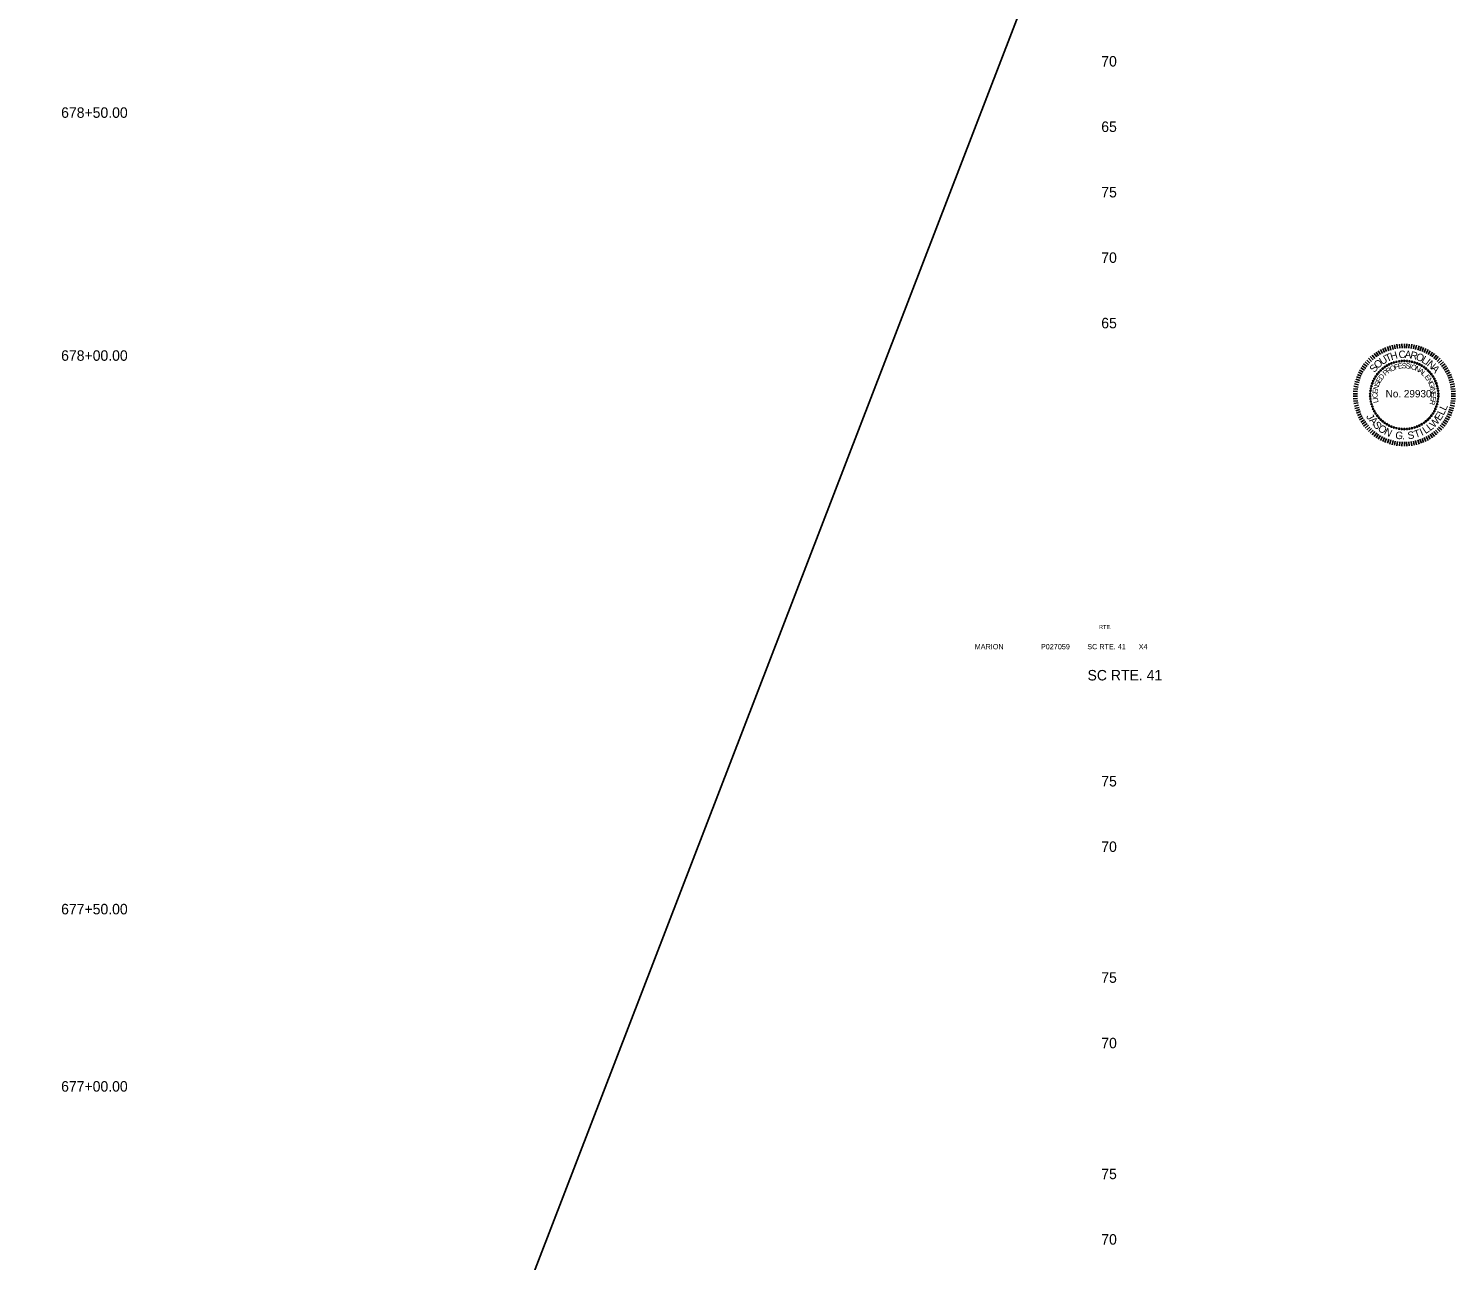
# Model space of a CAD drawing. Extents: x 952 to 1206, y 942 to 2399.
# Drawn here: x 1074.9 to 1184, y 1398.8 to 1492.9 of the extents above; entities that cross this region are included whole.
import ezdxf

# ---------------------------------------------------------------- set-up
doc = ezdxf.new("R2010")
doc.units = 0
for name, color, linetype in [('Default', 7, 'Continuous'), ('RD_SHT_TX', 7, 'Continuous'), ('RD_TX_PEShield', 7, 'Continuous'), ('RD_XS_TX_Elev_EX', 7, 'Continuous'), ('RD_XS_TX_Station', 7, 'Continuous')]:
    doc.layers.add(name, color=color, linetype=linetype)

# ---------------------------------------------------------------- blocks, each defined once
blk = doc.blocks.new('STILLWELL')
at = {"layer": 'RD_TX_PEShield'}
for p, q in [((-18.2, 30), (-19.9, 32.8)), ((-16.7, 30.8), (-18.2, 33.7)), ((-15.1, 31.6), (-16.5, 34.6)), ((-13.6, 32.3), (-14.8, 35.3)), ((-11.9, 32.9), (-13, 36)), ((-10.3, 33.4), (-11.2, 36.6)), ((-8.6, 33.9), (-9.4, 37.1)), ((-6.9, 34.3), (-7.5, 37.5)), ((-5.2, 34.6), (-5.7, 37.8)), ((-3.5, 34.8), (-3.8, 38)), ((-1.8, 34.9), (-1.9, 38.2)), ((0, 34.9), (0, 38.2)), ((1.7, 34.9), (1.9, 38.2)), ((3.4, 34.8), (3.7, 38)), ((5.2, 34.6), (5.6, 37.8)), ((6.9, 34.3), (7.5, 37.5)), ((8.6, 33.9), (9.3, 37.1)), ((10.2, 33.4), (11.2, 36.6)), ((11.9, 32.9), (13, 36)), ((13.5, 32.3), (14.7, 35.3)), ((15.1, 31.6), (16.5, 34.6)), ((16.6, 30.8), (18.2, 33.7)), ((18.2, 30), (19.8, 32.8)), ((-28.5, 20.9), (-31.1, 22.8)), ((-27.4, 22.2), (-29.9, 24.3)), ((-26.3, 23.5), (-28.7, 25.7)), ((-25.1, 24.7), (-27.4, 27.1)), ((-23.8, 25.9), (-26, 28.4)), ((-22.5, 27), (-24.5, 29.6)), ((-21.1, 28.1), (-23, 30.7)), ((-19.7, 29.1), (-21.5, 31.8)), ((19.6, 29.1), (21.4, 31.8)), ((21.1, 28.1), (23, 30.7)), ((22.4, 27), (24.5, 29.6)), ((23.8, 25.9), (25.9, 28.4)), ((25, 24.7), (27.3, 27.1)), ((26.2, 23.5), (28.6, 25.7)), ((27.4, 22.2), (29.9, 24.3)), ((28.5, 20.9), (31.1, 22.8)), ((-34.1, 10.2), (-37.2, 11.2)), ((-33.6, 11.8), (-36.6, 12.9)), ((-32.9, 13.4), (-35.9, 14.7)), ((-32.2, 15), (-35.1, 16.4)), ((-31.4, 16.5), (-34.2, 18.1)), ((-30.5, 18), (-33.3, 19.7)), ((-29.5, 19.4), (-32.2, 21.3)), ((29.5, 19.4), (32.2, 21.3)), ((30.4, 18), (33.2, 19.7)), ((31.3, 16.5), (34.2, 18.1)), ((32.1, 15), (35.1, 16.4)), ((32.9, 13.4), (35.9, 14.7)), ((33.5, 11.8), (36.6, 12.9)), ((34.1, 10.2), (37.2, 11.2)), ((-35.9, -0.1), (-39.2, 0)), ((-35.8, 1.7), (-39.1, 1.9)), ((-35.6, 3.4), (-38.9, 3.8)), ((-35.4, 5.1), (-38.6, 5.7)), ((-35.1, 6.8), (-38.2, 7.5)), ((-34.6, 8.5), (-37.8, 9.4)), ((34.6, 8.5), (37.7, 9.4)), ((35, 6.8), (38.2, 7.5)), ((35.3, 5.1), (38.5, 5.7)), ((35.6, 3.4), (38.8, 3.8)), ((35.7, 1.7), (39, 1.9)), ((35.8, -0.1), (39.1, 0)), ((-35.9, -1.8), (-39.2, -1.9)), ((-35.8, -3.5), (-39.1, -3.8)), ((-35.6, -5.3), (-38.9, -5.6)), ((-35.4, -7), (-38.6, -7.5)), ((-35.1, -8.7), (-38.2, -9.4)), ((-34.6, -10.4), (-37.8, -11.2)), ((34.6, -10.4), (37.7, -11.2)), ((35, -8.7), (38.2, -9.4)), ((35.3, -7), (38.5, -7.5)), ((35.6, -5.3), (38.8, -5.6)), ((35.7, -3.5), (39, -3.8)), ((35.8, -1.8), (39.1, -1.9)), ((-34.1, -12), (-37.2, -13)), ((-33.6, -13.6), (-36.6, -14.8)), ((-32.9, -15.3), (-35.9, -16.6)), ((-32.2, -16.8), (-35.1, -18.3)), ((-31.4, -18.4), (-34.2, -19.9)), ((-30.5, -19.9), (-33.3, -21.6)), ((-29.5, -21.3), (-32.2, -23.2)), ((29.5, -21.3), (32.2, -23.2)), ((30.4, -19.9), (33.2, -21.6)), ((31.3, -18.4), (34.2, -19.9)), ((32.1, -16.8), (35.1, -18.3)), ((32.9, -15.3), (35.9, -16.6)), ((33.5, -13.6), (36.6, -14.8)), ((34.1, -12), (37.2, -13)), ((-28.5, -22.7), (-31.1, -24.7)), ((-27.4, -24.1), (-29.9, -26.2)), ((-26.3, -25.4), (-28.7, -27.6)), ((-25.1, -26.6), (-27.4, -28.9)), ((-23.8, -27.8), (-26, -30.2)), ((-22.5, -28.9), (-24.5, -31.4)), ((-21.1, -29.9), (-23, -32.6)), ((-19.7, -30.9), (-21.5, -33.7)), ((-18.2, -31.8), (-19.9, -34.7)), ((-16.7, -32.7), (-18.2, -35.6)), ((16.6, -32.7), (18.2, -35.6)), ((18.2, -31.8), (19.8, -34.7)), ((19.6, -30.9), (21.4, -33.7)), ((21.1, -29.9), (23, -32.6)), ((22.4, -28.9), (24.5, -31.4)), ((23.8, -27.8), (25.9, -30.2)), ((25, -26.6), (27.3, -28.9)), ((26.2, -25.4), (28.6, -27.6)), ((27.4, -24.1), (29.9, -26.2)), ((28.5, -22.7), (31.1, -24.7)), ((-15.1, -33.5), (-16.5, -36.4)), ((-13.6, -34.1), (-14.8, -37.2)), ((-11.9, -34.8), (-13, -37.8)), ((-10.3, -35.3), (-11.2, -38.4)), ((-8.6, -35.8), (-9.4, -38.9)), ((-6.9, -36.1), (-7.5, -39.3)), ((-5.2, -36.4), (-5.7, -39.7)), ((-3.5, -36.6), (-3.8, -39.9)), ((-1.8, -36.8), (-1.9, -40)), ((0, -36.8), (0, -40.1)), ((1.7, -36.8), (1.9, -40)), ((3.4, -36.6), (3.7, -39.9)), ((5.2, -36.4), (5.6, -39.7)), ((6.9, -36.1), (7.5, -39.3)), ((8.6, -35.8), (9.3, -38.9)), ((10.2, -35.3), (11.2, -38.4)), ((11.9, -34.8), (13, -37.8)), ((13.5, -34.1), (14.7, -37.2)), ((15.1, -33.5), (16.5, -36.4))]:
    blk.add_line(p, q, dxfattribs=at)
for centre in [(-13.3, 21.5), (-11.6, 22.4), (-9.8, 23.2), (-7.9, 23.9), (-6, 24.4), (-4, 24.8), (-2, 25), (0, 25.1), (2, 25), (3.9, 24.8), (5.9, 24.4), (7.8, 23.9), (9.7, 23.2), (11.5, 22.4), (13.3, 21.5), (-22.9, 11.5), (-21.9, 13.2), (-20.7, 14.9), (-19.5, 16.4), (-18.1, 17.8), (-16.6, 19.2), (-15, 20.4), (15, 20.4), (16.5, 19.2), (18, 17.8), (19.4, 16.4), (20.7, 14.9), (21.8, 13.2), (22.9, 11.5), (-26.1, 0.1), (-25.9, 2.1), (-25.6, 4), (-25.1, 6), (-24.5, 7.9), (-23.8, 9.7), (23.7, 9.7), (24.5, 7.9), (25.1, 6), (25.5, 4), (25.8, 2.1), (26, 0.1), (-26.1, -1.9), (-25.9, -3.9), (-25.6, -5.9), (-25.1, -7.8), (-24.5, -9.7), (24.5, -9.7), (25.1, -7.8), (25.5, -5.9), (25.8, -3.9), (26, -1.9), (-23.8, -11.6), (-22.9, -13.4), (-21.9, -15.1), (-20.7, -16.7), (-19.5, -18.3), (-18.1, -19.7), (-16.6, -21), (-15, -22.2), (15, -22.2), (16.5, -21), (18, -19.7), (19.4, -18.3), (20.7, -16.7), (21.8, -15.1), (22.9, -13.4), (23.7, -11.6), (-13.3, -23.3), (-11.6, -24.3), (-9.8, -25.1), (-7.9, -25.8), (-6, -26.3), (-4, -26.7), (-2, -26.9), (0, -27), (2, -26.9), (3.9, -26.7), (5.9, -26.3), (7.8, -25.8), (9.7, -25.1), (11.5, -24.3), (13.3, -23.3)]:
    blk.add_circle(centre, 0.49, dxfattribs=at)
for s, height, rotation, p in [('C', 5.68, 4.076, (-4.2, 27.1)), ('A', 5.68, 355.3651, (0.1, 27.4)), ('S', 5.68, 49.6435, (-22.9, 15.8)), ('O', 5.68, 41.5972, (-20.4, 18.8)), ('U', 5.68, 32.2152, (-16.9, 21.8)), ('T', 5.68, 23.5044, (-13.2, 24.1)), ('H', 5.68, 16.1357, (-9.9, 25.6)), ('F', 3.92, 15.9995, (-7.1, 18.3)), ('E', 3.92, 8.9511, (-4.7, 19)), ('S', 3.92, 1.2546, (-1.9, 19.4)), ('S', 3.92, 353.558, (0.8, 19.5)), ('I', 3.92, 345.8615, (3.5, 19.2)), ('R', 5.68, 347.3188, (4.1, 27.1)), ('O', 3.92, 342.6583, (4.7, 19)), ('O', 5.68, 338.6079, (8.3, 26.2)), ('L', 5.68, 329.226, (12.6, 24.4)), ('I', 5.68, 322.5218, (15.5, 22.8)), ('N', 5.68, 319.1729, (16.8, 21.8)), ('E', 3.92, 60.2341, (-18.5, 7.9)), ('D', 3.92, 52.5376, (-17.1, 10.3)), ('P', 3.92, 41.0022, (-14.5, 13.5)), ('R', 3.92, 33.3057, (-12.5, 15.3)), ('O', 3.92, 24.9735, (-10, 16.9)), ('N', 3.92, 333.6842, (7.7, 18)), ('A', 3.92, 325.3521, (10.4, 16.7)), ('L', 3.92, 317.6555, (12.6, 15.1)), ('E', 3.92, 308.0396, (15.1, 12.8)), ('N', 3.92, 300.343, (16.8, 10.6)), ('A', 5.68, 310.4621, (20.1, 19)), ('C', 3.92, 92.2915, (-20.4, -3.2)), ('E', 3.92, 83.9594, (-20.5, -0.2)), ('N', 3.92, 76.2628, (-20.2, 2.5)), ('S', 3.92, 67.9307, (-19.5, 5.4)), ('G', 3.92, 292.0109, (18.3, 8.1)), ('I', 3.92, 283.0368, (19.5, 5.1)), ('N', 3.92, 279.8336, (19.8, 4)), ('E', 3.92, 271.5014, (20.3, 1.1)), ('I', 3.92, 95.4947, (-20.2, -4.3)), ('L', 3.92, 101.9075, (-19.7, -6.6)), ('R', 3.92, 256.1083, (20.1, -4.4)), ('E', 3.92, 263.8049, (20.4, -1.7)), ('L', 5.68, 65.098, (31.6, -13.3)), ('J', 5.68, 299.033, (-29.4, -17.3)), ('A', 5.68, 310.5887, (-27.2, -20.6)), ('S', 5.68, 310.5887, (-24.3, -24)), ('W', 5.68, 47.0518, (22.6, -26.4)), ('E', 5.68, 56.4327, (27.3, -21.1)), ('L', 5.68, 65.098, (30, -16.9)), ('O', 5.68, 321.0072, (-20.8, -27.4)), ('N', 5.68, 333.4326, (-16, -30.8)), ('G', 5.68, 352.2045, (-7.2, -34.2)), ('S', 5.68, 8.0826, (2.9, -34.8)), ('T', 5.68, 18.9019, (8.5, -33.9)), ('I', 5.68, 25.3991, (13.3, -32.2)), ('L', 5.68, 34.0644, (16.2, -30.9)), ('L', 5.68, 37.6708, (19.6, -28.7)), ('.', 5.68, 0.8698, (-1.8, -34.9))]:
    blk.add_text(s, height=height, rotation=rotation, dxfattribs=at).set_placement(p)
blk.add_text('No. 29930', height=5.68, dxfattribs=at).set_placement((-14.3, -2.8))

msp = doc.modelspace()

# ---------------------------------------------------------------- linework, layer by layer
at = {"layer": 'RD_SHT_TX'}
msp.add_line((951.99, 979.01), (1182.92, 1577.73), dxfattribs=at)

# ---------------------------------------------------------------- block references
at = {"layer": 'Default', "xscale": 0.1, "yscale": 0.10000000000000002}
msp.add_blockref('STILLWELL', (1180.08, 1465), dxfattribs=at)

# ---------------------------------------------------------------- texts
at = {"layer": 'RD_SHT_TX'}
for s, height, p in [('RTE.', 0.3, (1156.76, 1447.03)), ('MARION', 0.4, (1147.25, 1445.48)), ('P027059', 0.4, (1152.31, 1445.48)), ('SC RTE. 41', 0.4, (1155.85, 1445.48)), ('X4', 0.4, (1159.78, 1445.48)), ('SC RTE. 41', 0.8, (1155.87, 1443.1))]:
    msp.add_text(s, height=height, dxfattribs=at).set_placement(p)
at = {"layer": 'RD_XS_TX_Elev_EX'}
for s, p in [('70', (1156.92, 1490)), ('65', (1156.92, 1485)), ('75', (1156.92, 1480)), ('70', (1156.92, 1475)), ('65', (1156.92, 1470)), ('75', (1156.92, 1435)), ('70', (1156.92, 1430)), ('75', (1156.92, 1420)), ('70', (1156.92, 1415)), ('75', (1156.92, 1405)), ('70', (1156.92, 1400))]:
    msp.add_text(s, height=0.8, dxfattribs=at).set_placement(p)
at = {"layer": 'RD_XS_TX_Station'}
for s, p in [('678+50.00', (1077.44, 1486.08)), ('678+00.00', (1077.44, 1467.52)), ('677+50.00', (1077.44, 1425.23)), ('677+00.00', (1077.44, 1411.69))]:
    msp.add_text(s, height=0.8, dxfattribs=at).set_placement(p)

doc.saveas('drawing.dxf')
